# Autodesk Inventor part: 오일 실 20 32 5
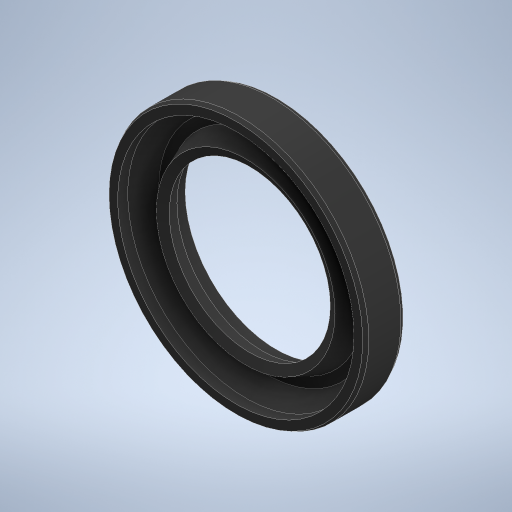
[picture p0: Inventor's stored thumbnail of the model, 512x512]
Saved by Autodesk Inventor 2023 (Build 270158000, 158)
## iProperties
Created: 2026-07
Part Number: 오일 실 20 32 5
Material: 고무
Description: 오일 실 - 스프링 장착, 비스프링, 고무 덮개 G
Document SubType Name: Modeling
Designer: home
Density: 0.93 g/cm^3
Appearance: 기본값
Author: jhkim
Sending System: Autodesk Inventor 2027
Preprocessor: ST-DEVELOPER v20.1
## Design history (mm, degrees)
feature "Solid1"
node "솔리드1"
